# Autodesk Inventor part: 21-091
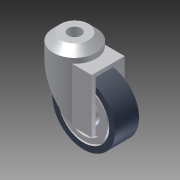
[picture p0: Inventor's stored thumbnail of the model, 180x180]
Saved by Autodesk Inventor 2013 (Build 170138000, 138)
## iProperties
Created: 2004-11
Part Number: 21-091
Document SubType Name: Modeling
Designer: Autodesk, Inc.
Manufacturer: Standard
Standards Organization: Custom
Description: CASTER, SWIVEL
Vendor: PARKER IPS
Mass: 51.9098 g
Surface Area: 184.177 cm^2
Volume: 51.9098 cm^3
Density: 1 g/cm^3
Material: Allgemein
CAGE: 1LJX3
Dept. ID: Product Design
Description #2: ---
Finish #1: ---
Finish #2: ---
Material ID: ---
Project Number: ---
Description: Casters
Order Number: 21-091
Selection: Casters
Supplier: Parker Hannifin Corp., Industrial Profile Systems Div.
Author: Autodesk, Inc.
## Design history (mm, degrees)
feature "Base1"
sketch "Sketch1"
  geometry: C1 r 15.345 at (0, 0) reference; C2 r 19.05 at (0, 0); C3 r 20.32 at (0, 0)
  constraints: 2 centre point, 2 coincident
  dimensions: "d2" = 38.1 diameter of C2; "d3" = 1.27 radial gap between concentric circles of C2 C3
extrude "Extrusion1" cut sketch "Sketch1" distance "d0" = 2.54; taper "d1" = 0 deg
mirror "Mirror1"
node "Ground"
body "Solid1"
